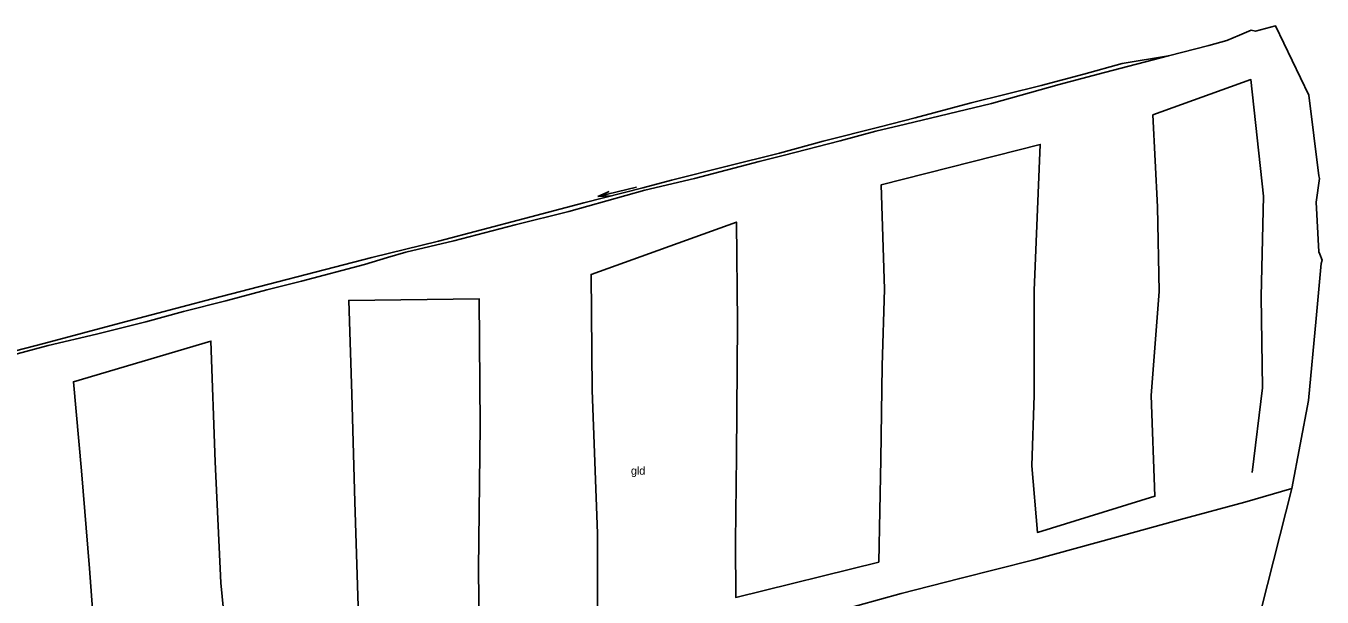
# Model space of a CAD drawing. Extents: x 154825 to 158680, y 370717 to 378075.
# Drawn here: x 157480 to 157642, y 372849.4 to 372920.9 of the extents above; entities that cross this region are included whole.
import ezdxf

# ---------------------------------------------------------------- set-up
doc = ezdxf.new("R2010")
doc.units = 0
for name, color, linetype in [('grasland_productiegrasl(vs)', 7, 'Continuous'), ('hoogteverschillijn', 7, 'Continuous'), ('insteek sloot', 7, 'Continuous'), ('Sloot bodem', 7, 'Continuous'), ('stroomrichting  watergangen', 7, 'Continuous'), ('vlak_Grasland', 7, 'Continuous'), ('vlak_Grazige_vegetatie', 7, 'Continuous')]:
    doc.layers.add(name, color=color, linetype=linetype)

msp = doc.modelspace()

# ---------------------------------------------------------------- linework, layer by layer
at = {"layer": 'hoogteverschillijn'}
for points in [[(157633.71, 372920.22), (157636.19, 372920.86), (157640.34, 372912.19), (157641.59, 372902.11)], [(157551.47, 372843.22), (157551.44, 372857.37), (157550.8, 372875.29), (157550.65, 372889.78), (157568.82, 372896.33), (157568.95, 372883.74), (157568.83, 372867.09), (157568.71, 372856.35), (157568.73, 372849.4), (157586.6, 372853.81), (157586.87, 372866.62), (157587.02, 372878.35), (157587.31, 372887.93), (157586.91, 372901), (157606.8, 372906.04), (157606.02, 372887.78), (157606.02, 372874.7), (157605.73, 372865.84), (157606.43, 372857.51), (157621.12, 372862.04), (157620.65, 372874.64), (157621.64, 372887.66), (157621.44, 372898.25), (157620.88, 372909.73), (157633.11, 372914.15), (157634.69, 372899.55), (157634.39, 372887.02), (157634.56, 372875.62), (157633.28, 372865.02)], [(157641.89, 372891.16), (157641.27, 372884.26), (157640.31, 372874.01), (157638.22, 372862.99), (157632.34, 372861.32), (157624.32, 372859.12), (157616.33, 372856.92), (157605.97, 372854.08), (157596.73, 372851.76), (157589.42, 372849.87), (157581.27, 372847.62)], [(157521.66, 372844.37), (157521.14, 372861.35), (157520.74, 372874.82), (157520.38, 372886.53), (157536.67, 372886.73), (157536.78, 372870.86), (157536.6, 372852.98), (157536.76, 372837.33)], [(157488.82, 372841.7), (157487.98, 372853.02), (157486.98, 372865.21), (157485.97, 372876.37), (157503.14, 372881.44), (157503.66, 372866.36), (157504.38, 372851.2), (157505.78, 372837.11)]]:
    msp.add_lwpolyline(points, dxfattribs=at)
at = {"layer": 'insteek sloot'}
for points in [[(157472.07, 372878.02), (157482.82, 372880.89), (157488.84, 372882.32), (157495.03, 372883.87), (157499.74, 372885.14), (157505, 372886.46), (157510.12, 372887.85), (157514.48, 372888.95), (157522.34, 372891.03), (157525.22, 372891.9), (157527.5, 372892.57), (157533.5, 372894), (157541.18, 372896), (157547.87, 372897.66), (157557.37, 372900.33), (157563.58, 372901.79), (157571.66, 372903.9), (157574.68, 372904.66), (157581.79, 372906.5), (157586.24, 372907.68), (157589.94, 372908.56), (157600.71, 372911.17), (157609.17, 372913.54), (157614.83, 372915.05), (157622.81, 372917.11), (157627.85, 372918.42), (157630.09, 372919.02), (157631.71, 372919.72), (157633.14, 372920.32)], [(157641.69, 372901.79), (157641.29, 372898.8), (157641.59, 372892.62), (157641.72, 372892.3), (157642.01, 372891.57)]]:
    msp.add_lwpolyline(points, dxfattribs=at)
at = {"layer": 'Sloot bodem'}
msp.add_lwpolyline([(157617.01, 372916.14), (157612.22, 372914.84), (157606.89, 372913.41), (157598.14, 372911.23), (157591.15, 372909.36), (157586.77, 372908.25), (157579.66, 372906.44), (157574.19, 372904.95), (157567.68, 372903.3), (157560.7, 372901.58), (157557.14, 372900.6), (157549.73, 372898.74), (157542.35, 372896.78), (157531.59, 372893.93), (157523.26, 372891.9), (157503.3, 372886.73), (157491.93, 372883.72), (157482.25, 372881.15), (157474.03, 372879.01), (157470.5, 372878.27)], dxfattribs=at)
at = {"layer": 'stroomrichting  watergangen'}
for p, q in [((157556.34, 372900.71), (157551.49, 372899.52)), ((157551.49, 372899.52), (157552.93, 372900.16)), ((157551.51, 372899.51), (157553.08, 372899.62))]:
    msp.add_line(p, q, dxfattribs=at)
at = {"layer": 'vlak_Grasland'}
msp.add_lwpolyline([(157472.07, 372878.02), (157482.82, 372880.89), (157488.84, 372882.32), (157495.03, 372883.87), (157499.74, 372885.14), (157505, 372886.46), (157510.12, 372887.85), (157514.48, 372888.95), (157522.34, 372891.03), (157525.22, 372891.9), (157527.5, 372892.57), (157533.5, 372894), (157541.18, 372896), (157547.87, 372897.66), (157557.37, 372900.33), (157563.58, 372901.79), (157571.66, 372903.9), (157574.68, 372904.66), (157581.79, 372906.5), (157586.24, 372907.68), (157589.94, 372908.56), (157600.71, 372911.17), (157609.17, 372913.54), (157614.83, 372915.05), (157622.81, 372917.11), (157627.85, 372918.42), (157630.09, 372919.02), (157631.71, 372919.72), (157633.14, 372920.32), (157633.71, 372920.22), (157636.19, 372920.86), (157640.34, 372912.19), (157641.59, 372902.11), (157641.69, 372901.79), (157641.29, 372898.8), (157641.59, 372892.62), (157641.72, 372892.3), (157642.01, 372891.57), (157641.89, 372891.16), (157641.27, 372884.26), (157640.31, 372874.01), (157638.22, 372862.99), (157631.39, 372836.05)], dxfattribs=at)
at = {"layer": 'vlak_Grazige_vegetatie'}
msp.add_lwpolyline([(157474.03, 372879.01), (157482.25, 372881.15), (157491.93, 372883.72), (157503.3, 372886.73), (157523.26, 372891.9), (157531.59, 372893.93), (157542.35, 372896.78), (157549.73, 372898.74), (157557.14, 372900.6), (157560.7, 372901.58), (157567.68, 372903.3), (157574.19, 372904.95), (157579.66, 372906.44), (157586.77, 372908.25), (157591.15, 372909.36), (157598.14, 372911.23), (157606.89, 372913.41), (157612.22, 372914.84), (157617.01, 372916.14), (157622.81, 372917.11), (157614.83, 372915.05), (157609.17, 372913.54), (157600.71, 372911.17), (157589.94, 372908.56), (157586.24, 372907.68), (157581.79, 372906.5), (157574.68, 372904.66), (157571.66, 372903.9), (157563.58, 372901.79), (157557.37, 372900.33), (157547.87, 372897.66), (157541.18, 372896), (157533.5, 372894), (157527.5, 372892.57), (157525.22, 372891.9), (157522.34, 372891.03), (157514.48, 372888.95), (157510.12, 372887.85), (157505, 372886.46), (157499.74, 372885.14), (157495.03, 372883.87), (157488.84, 372882.32), (157482.82, 372880.89), (157472.07, 372878.02)], dxfattribs=at)

# ---------------------------------------------------------------- texts
at = {"layer": 'grasland_productiegrasl(vs)'}
msp.add_text('gld', height=1, dxfattribs=at).set_placement((157555.64, 372864.74))

doc.saveas('drawing.dxf')
